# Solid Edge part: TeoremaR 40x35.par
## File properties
Title: Terorema R 40x35
Author: DESYS
Template: Normal.par
Last saved by: i.fialdini
Revision: 29
Application: Solid Edge
Stile della faccia: Model Default
Coef. of Thermal Exp: 0.0
Thermal Conductivity: 0.0
Specific Heat: 0.0
Modulus of Elasticity: 0.0
Poisson's Ratio: 0.0
Yield Stress: 0.0
Ultimate Stress: 0.0
Elongation: 0.0
Tipo di contenuto documento: 0
Precisione: 0.990
Document Number: 5001
Revision: 0
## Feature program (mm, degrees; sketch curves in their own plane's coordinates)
sketch for "unnamed Protrusion 1" plane through (0, 0, 0) normal (0, 0, 1) x-axis (1, 0, 0)
  line (-175, -205) -> (175, -205)
  line (175, -205) -> (175, 205)
  line (175, 205) -> (-175, 205)
  line (-175, 205) -> (-175, -205)
  dimension (linear) = 175
  dimension (linear) = 175
extrude "unnamed Protrusion 1" add finite 140 along +normal
lofted cutout "unnamed LoftedCutout 1"
sketch for "ExtrudedCutout_6" plane through (-40, 0, 0) normal (1, 0, 0) x-axis (0, 1, 0)
  line (193, 0) -> (190.8118, 12)
  line (190.8118, 12) -> (-190.8118, 12)
  line (-193, 0) -> (-190.8118, 12)
  line (193, 0) -> (-193, 0)
extrude "ExtrudedCutout_6" cut finite 119 along -normal
sketch for "ExtrudedCutout_2" plane through (0, 0, 140) normal (0, 0, 1) x-axis (0, 1, 0)
  line (-140, -125) -> (140, -125)
  arc centre (140, -110) radius 15 from (140, -125) to (155, -110) ccw
  line (155, -110) -> (155, 155)
  line (-155, 155) -> (155, 155)
  line (-155, 155) -> (-155, -110)
  arc centre (-140, -110) radius 15 from (-155, -110) to (-140, -125) ccw
extrude "ExtrudedCutout_2" cut finite 45 along -normal  DraftAngle = 10 deg
sketch for "Scavo3" plane through (0, 0, 140) normal (0, 0, 1) x-axis (0, -1, 0)
  line (-155, -155) -> (155, -155)
  line (155, -155) -> (155, -55)
  line (155, -55) -> (-155, -55)
  line (-155, -55) -> (-155, -155)
extrude "Scavo3" cut finite 115 along -normal  Treatment1_DraftAngle = 10 deg
fillet "unnamed Round 1"
sketch for "ExtrudedProtrusion_2" plane through (0, 0, 95) normal (0, 0, 1) x-axis (0, -1, 0)
  circle centre (0, 50) radius 35
extrude "ExtrudedProtrusion_2" add finite 40 along +normal
sketch for "ExtrudedProtrusion_3" plane through (0, 0, 0) normal (0, -1, 0) x-axis (1, 0, 0)
  line (28.9545, 125) -> (-43.6813, 125)
  arc centre (-43.6813, 80) radius 45 from (-88.3888, 85.1225) to (-43.6813, 125) cw
  line (-88.3888, 85.1225) -> (-95.2776, 25)
  line (-95.2776, 25) -> (-75.2776, 25)
  line (-75.2776, 25) -> (-65.8489, 78.473)
  arc centre (-46.1527, 75) radius 20 from (-65.8489, 78.473) to (-46.1527, 95) cw
  line (-46.1527, 95) -> (28.9545, 95)
  line (28.9545, 95) -> (28.9545, 125)
  dimension (linear) = 95.2776
extrude "ExtrudedProtrusion_3" add finite 45 symmetric
sketch for "Foro_1" plane through (12.5, 0.0692, 135) normal (0, 0, 1) x-axis (0, -1, 0)
  hole centre (0.0692, 37.5) bore radius 25
hole "Foro_1" diameter 50 through
sketch for "Foro_2" plane through (-40, 0, 46) normal (1, 0, 0) x-axis (0, -1, 0)
  hole centre (0, 4) bore radius 10
hole "Foro_2" diameter 20 finite
fillet "Rotondo_7" radius 5
fillet "Rotondo_14" radius 5
fillet "Rotondo_17" radius 15
fillet "Rotondo_18" radius 6
fillet "Rotondo_19" radius 6
fillet "Rotondo_20" radius 6
sketch for "Foro_4" plane through (-155, 0, 12) normal (0, 0, -1) x-axis (0, -1, 0)
  hole centre (0, -40) bore radius 18
hole "Foro_4" diameter 36 through
fillet "Rotondo_21" radius 15
fillet "Rotondo_22" radius 5
sketch for "Foro_5" plane through (-175, 0, 50) normal (-1, 0, 0) x-axis (0, -1, 0)
  hole centre (-183, 68) bore radius 8
hole "Foro_5" finite
fillet "Rotondo_26" radius 6
sketch for "ExtrudedCutout_7" plane through (-175, 0, 72.5) normal (-1, 0, 0) x-axis (0, 1, 0)
extrude "ExtrudedCutout_7" cut finite 60 along -normal
sketch for "unnamed Cutout 1" #1 plane through (-175, 0, 72.5) normal (-1, 0, 0) x-axis (0, 1, 0)
  line (95, 7.5) -> (85, 7.5)
  arc centre (85, 17.5) radius 10 from (85, 7.5) to (85, 27.5) cw
  line (85, 27.5) -> (95, 27.5)
  arc centre (95, 17.5) radius 10 from (95, 7.5) to (95, 27.5) ccw
sketch for "unnamed Cutout 1" #2 plane through (-175, 0, 72.5) normal (-1, 0, 0) x-axis (0, 1, 0)
  line (-95, 7.5) -> (-85, 7.5)
  line (-85, 27.5) -> (-95, 27.5)
  dimension (linear) = 85
  dimension (linear) = 85
extrude "unnamed Cutout 1" cut through along -normal
fillet "Rotondo_31" radius 15
fillet "Rotondo_32" radius 5
fillet "Rotondo_33" radius 5
fillet "Rotondo_34" radius 5
fillet "Rotondo_35" radius 5
fillet "Rotondo_36" radius 5
fillet "Rotondo_37" radius 5
fillet "Rotondo_38" radius 5
fillet "Rotondo_39" radius 2
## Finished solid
Body 1: solid body, 168 faces, 371 edges, 204 vertices.
  Faces by surface: cylinder 76, plane 32, blend 25, torus 23, sphere 10, cone 2
  Edges by curve: circle 160, line 151, ellipse 54, intersection 6
Bounding box of the edges (mm; curved faces can reach further): 350.000 x 410.000 x 140.000, from (-175, -205, 0) to (175, 205, 140).
Cylindrical faces by radius (mm): R5 x43, R6 x14, R8 x1, R10 x5, R15 x6, R18 x1, R20 x2, R25 x1, R35 x1, R45 x1, R97.25 x1
Conical faces (half-angle, radius in mm at the cone's reference point): 10 deg R15 x2
Toroidal faces (ring radius, tube radius in mm): R1 r5 x8, R2.8698 r5 x2, R12 r2 x1, R19.1955 r5 x2, R23 r5 x1, R25 r5 x2, R30 r5 x1, R40 r5 x4, R40 r15 x1, R102.25 r5 x1
Spherical faces by radius (mm): R5 x10
Planar faces by outward normal: +x 3, +y 2, +z 8, -x 2, -y 2, -z 5, oblique 10
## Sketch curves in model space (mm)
line (143, -177.5, 85) -> (-40, -177.5, 85)
line (-40, -177.5, 85) -> (-40, 177.5, 85)
line (-40, 177.5, 85) -> (143, 177.5, 85)
line (143, 177.5, 85) -> (143, -177.5, 85)
line (163, -193, 0) -> (-40, -193, 0)
line (-40, -193, 0) -> (-40, 193, 0)
line (-40, 193, 0) -> (163, 193, 0)
line (163, 193, 0) -> (163, -193, 0)
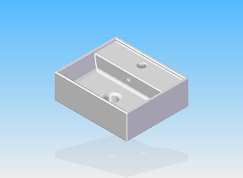
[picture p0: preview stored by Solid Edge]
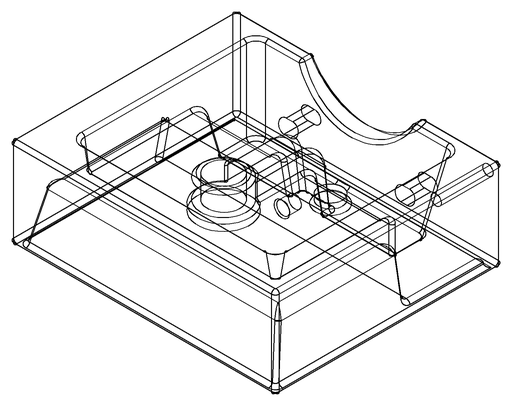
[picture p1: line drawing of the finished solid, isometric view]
